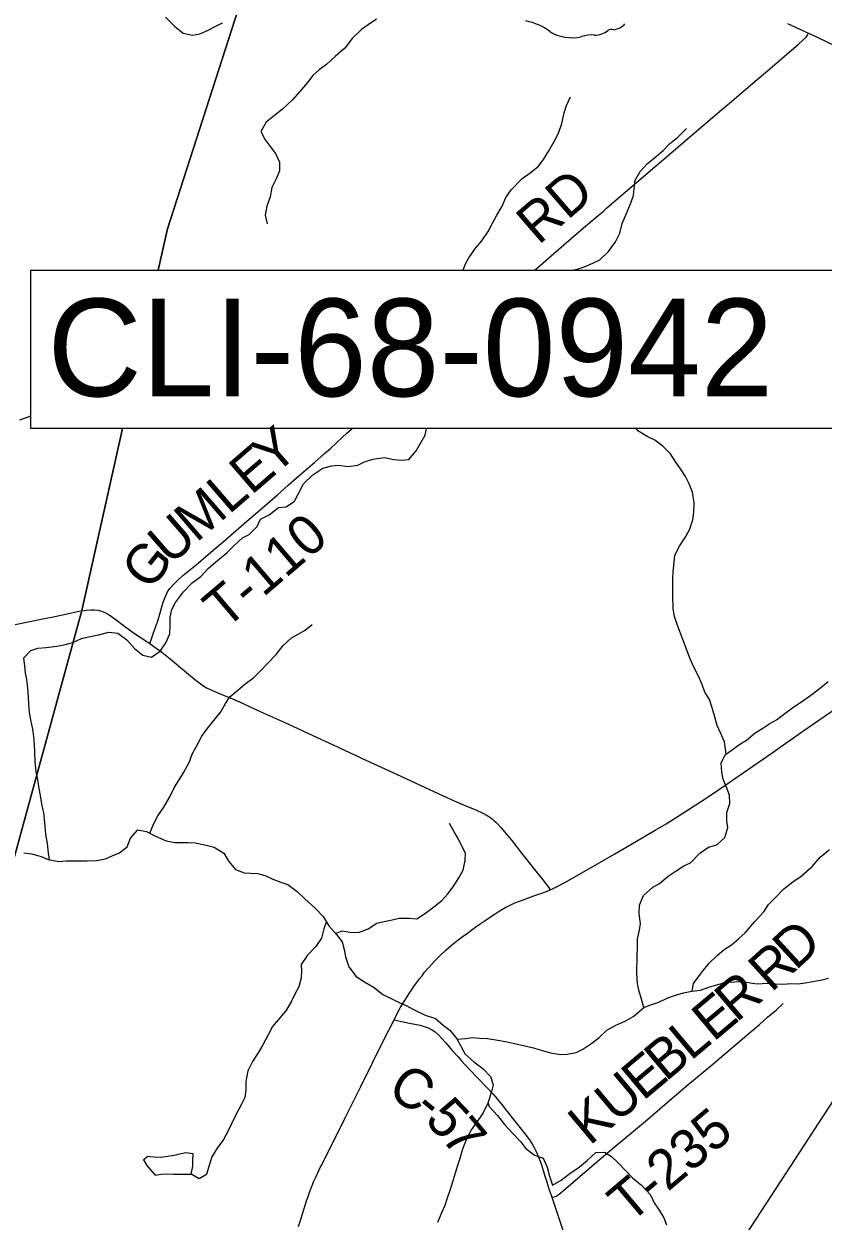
# Model space of a CAD drawing. Extents: x 0 to 34, y 0 to 22.
# Drawn here: x 3.586 to 4.732, y 15.651 to 17.368 of the extents above; entities that cross this region are included whole.
import ezdxf

# ---------------------------------------------------------------- set-up
doc = ezdxf.new("R2010")
doc.units = 0
for name, color, linetype in [('GM_X_County_Road', 7, 'Continuous'), ('GM_X_County_Road_Text', 7, 'Continuous'), ('GM_X_Minor_Lake', 7, 'Continuous'), ('GM_X_Minor_River', 7, 'Continuous'), ('GM_X_Rail_Line', 7, 'Continuous'), ('GM_X_State_Route', 7, 'Continuous'), ('GM_X_State_Shield', 7, 'Continuous'), ('GM_X_Township_Road', 7, 'Continuous'), ('GM_X_Township_Road_Text', 7, 'Continuous'), ('GM_X_US_Route', 7, 'Continuous'), ('SH_Text', 7, 'Continuous')]:
    doc.layers.add(name, color=color, linetype=linetype)

msp = doc.modelspace()

# ---------------------------------------------------------------- linework, layer by layer
at = {"layer": 'GM_X_County_Road'}
for points in [[(4.117, 15.9393), (4.1256, 15.9374), (4.1389, 15.9345), (4.1542, 15.9314), (4.1602, 15.9298), (4.1656, 15.9278), (4.1707, 15.9253), (4.1759, 15.9217), (4.1806, 15.9175), (4.185, 15.913), (4.1911, 15.906), (4.2004, 15.8951), (4.2086, 15.8859), (4.2107, 15.8835), (4.2132, 15.8809), (4.2251, 15.8681), (4.2504, 15.8416), (4.2588, 15.8324), (4.2617, 15.8292), (4.2647, 15.8256), (4.268, 15.8217), (4.2713, 15.8178), (4.2755, 15.8124), (4.3048, 15.7753), (4.3111, 15.7668), (4.3136, 15.7631), (4.3159, 15.7595), (4.3181, 15.7553), (4.3203, 15.7512), (4.3222, 15.7468), (4.3242, 15.742), (4.3262, 15.7365), (4.3286, 15.7297), (4.3332, 15.7148), (4.3348, 15.7096), (4.3368, 15.7033), (4.3383, 15.6982), (4.3397, 15.6941), (4.3429, 15.6846)], [(4.3429, 15.6846), (4.3609, 15.6317)]]:
    msp.add_lwpolyline(points, dxfattribs=at)
at = {"layer": 'GM_X_Minor_Lake'}
for points in [[(3.8258, 15.7177), (3.8283, 15.7291), (3.8284, 15.7371), (3.8289, 15.7469), (3.8183, 15.7486), (3.8095, 15.7464), (3.8016, 15.7446), (3.7924, 15.7429), (3.7822, 15.7415), (3.7727, 15.742), (3.767, 15.7428)], [(3.767, 15.7428), (3.764, 15.7433), (3.7579, 15.7384), (3.7627, 15.73), (3.7675, 15.7238), (3.7742, 15.7165), (3.783, 15.7179), (3.7913, 15.7182), (3.8008, 15.7177), (3.8103, 15.718), (3.8258, 15.7177)]]:
    msp.add_lwpolyline(points, dxfattribs=at)
at = {"layer": 'GM_X_Minor_River'}
for points in [[(3.7893, 17.3776), (3.8024, 17.3642), (3.8144, 17.3545), (3.828, 17.3517), (3.8386, 17.3534), (3.8493, 17.3582), (3.8615, 17.3645), (3.8711, 17.3693)], [(4.0918, 17.3746), (4.0799, 17.3664), (4.0704, 17.3597), (4.0569, 17.347), (4.0465, 17.3327), (4.0323, 17.3212), (4.02, 17.3096), (4.01, 17.3025), (4.0004, 17.2939), (3.993, 17.2837), (3.9815, 17.2702), (3.9711, 17.259), (3.9572, 17.2455), (3.9457, 17.2365), (3.9338, 17.2268), (3.9257, 17.2133), (3.9319, 17.2014), (3.9394, 17.1918), (3.9468, 17.1819), (3.9527, 17.1693), (3.9525, 17.1571), (3.9486, 17.1465), (3.9419, 17.133), (3.9391, 17.1197), (3.9347, 17.1065), (3.9323, 17.0936), (3.9351, 17.081)], [(4.2159, 17.0143), (4.219, 17.0225), (4.2241, 17.0323), (4.2338, 17.0462), (4.2427, 17.0567), (4.2519, 17.0699), (4.2582, 17.0819), (4.2644, 17.0933), (4.2718, 17.1064), (4.2773, 17.1185), (4.285, 17.1298), (4.3004, 17.1459), (4.3119, 17.1541), (4.3234, 17.1634), (4.3312, 17.1732), (4.3389, 17.1856), (4.3463, 17.1992), (4.3526, 17.2109), (4.3573, 17.2249), (4.3606, 17.24), (4.3642, 17.2506), (4.37, 17.263)], [(4.3743, 17.0143), (4.3763, 17.015), (4.3873, 17.0183), (4.4018, 17.0246), (4.4121, 17.0294), (4.4244, 17.0413), (4.4345, 17.0552), (4.4407, 17.0677), (4.444, 17.0813), (4.4499, 17.0949), (4.4561, 17.1096), (4.4601, 17.1217), (4.461, 17.1312), (4.4627, 17.1437), (4.4697, 17.1561), (4.4801, 17.1674), (4.4928, 17.1775), (4.5027, 17.186), (4.5116, 17.1958), (4.5239, 17.2051), (4.5362, 17.2175)], [(3.5803, 16.7996), (3.5936, 16.8048), (3.596, 16.8059)], [(3.6228, 16.1689), (3.6217, 16.1784), (3.62, 16.1921), (3.6179, 16.205), (3.6166, 16.2164), (3.6156, 16.227), (3.6146, 16.2365), (3.6124, 16.2461), (3.6107, 16.2579), (3.6075, 16.2738), (3.6062, 16.2841), (3.604, 16.2944), (3.6024, 16.31), (3.6018, 16.3233), (3.6016, 16.3339), (3.6006, 16.3457), (3.5989, 16.3563), (3.596, 16.3693), (3.5943, 16.3799), (3.5933, 16.3917), (3.5927, 16.4024), (3.5921, 16.4149), (3.5904, 16.4271), (3.5887, 16.4366), (3.5877, 16.4465), (3.5863, 16.4586), (3.596, 16.4691), (3.6063, 16.4724), (3.618, 16.4734), (3.6336, 16.4751), (3.6439, 16.4772), (3.6564, 16.4805), (3.669, 16.486), (3.6793, 16.4885), (3.6949, 16.4917), (3.7082, 16.4953), (3.7207, 16.4936), (3.7338, 16.484), (3.745, 16.472), (3.7566, 16.462), (3.7691, 16.4596), (3.7814, 16.4681), (3.7895, 16.4798), (3.7954, 16.493), (3.7959, 16.5044), (3.7957, 16.5169), (3.7985, 16.5279), (3.8036, 16.5377), (3.8152, 16.5531), (3.8275, 16.5658), (3.8398, 16.5751), (3.851, 16.5868), (3.864, 16.598), (3.8775, 16.6096), (3.8871, 16.6193), (3.8994, 16.6305), (3.9093, 16.6353), (3.9205, 16.6466), (3.9255, 16.6571), (3.9381, 16.6634), (3.9512, 16.6739), (3.9622, 16.6748), (3.9741, 16.683), (3.9799, 16.694), (3.9873, 16.7079), (4.0004, 16.721), (4.015, 16.7303), (4.0279, 16.7339), (4.0374, 16.7346), (4.051, 16.7329), (4.0651, 16.7349), (4.0746, 16.7394), (4.0864, 16.7434), (4.1031, 16.7458), (4.1168, 16.743), (4.127, 16.7421), (4.138, 16.7427), (4.1484, 16.7551), (4.1542, 16.7656), (4.1616, 16.7777), (4.1633, 16.7873)], [(4.593, 16.3203), (4.5905, 16.3379), (4.585, 16.3509), (4.5802, 16.3612), (4.5774, 16.3719), (4.573, 16.3867), (4.569, 16.3985), (4.5627, 16.4093), (4.5591, 16.4188), (4.5543, 16.4303), (4.5466, 16.4448), (4.5414, 16.457), (4.536, 16.4707), (4.5308, 16.4845), (4.5265, 16.4963), (4.5228, 16.5062), (4.5192, 16.5177), (4.5171, 16.5287), (4.5166, 16.5477), (4.5168, 16.5617), (4.5166, 16.5724), (4.5171, 16.5819), (4.5184, 16.5955), (4.5193, 16.6057), (4.526, 16.6186), (4.5345, 16.631), (4.5407, 16.6419), (4.5451, 16.6563), (4.5468, 16.6673), (4.547, 16.6809), (4.5449, 16.6961), (4.5398, 16.708), (4.5346, 16.7183), (4.5276, 16.7294), (4.5209, 16.739), (4.5131, 16.7512), (4.5023, 16.762), (4.4906, 16.7705), (4.4797, 16.776), (4.4673, 16.7837), (4.4638, 16.7873)], [(3.7667, 16.2067), (3.7725, 16.2207), (3.7783, 16.2317), (3.7868, 16.2444), (3.7954, 16.2588), (3.802, 16.2731), (3.8086, 16.2833), (3.8156, 16.2945), (3.823, 16.3085), (3.8277, 16.3202), (3.8359, 16.336), (3.8414, 16.3462), (3.8491, 16.3564), (3.8584, 16.3684), (3.8688, 16.3808), (3.8754, 16.3928), (3.8816, 16.4026), (3.8932, 16.4127), (3.9028, 16.4205), (3.9158, 16.4302), (3.9254, 16.4396), (3.9354, 16.4501), (3.9477, 16.4632), (3.9578, 16.476), (3.9701, 16.4872), (3.9796, 16.4924), (3.9896, 16.4983), (3.9996, 16.5062)], [(4.475, 15.9568), (4.4718, 15.9686), (4.4678, 15.9819), (4.466, 15.9915), (4.4651, 16.0063), (4.4655, 16.031), (4.466, 16.0435), (4.4658, 16.0552), (4.469, 16.0677), (4.4703, 16.0772), (4.4682, 16.0913), (4.4688, 16.1034), (4.4747, 16.1174), (4.4881, 16.1293), (4.4977, 16.1349), (4.51, 16.145), (4.5199, 16.1521), (4.5326, 16.1599), (4.5421, 16.1643), (4.5552, 16.1782), (4.5675, 16.1867), (4.5796, 16.1904), (4.5912, 16.2005), (4.5955, 16.2148), (4.5942, 16.2243), (4.594, 16.2365), (4.5983, 16.2497), (4.5977, 16.2615), (4.5941, 16.2714), (4.589, 16.2844), (4.5868, 16.2943), (4.5859, 16.3076), (4.5921, 16.3196), (4.6017, 16.3264), (4.6113, 16.3334), (4.622, 16.3401), (4.6347, 16.351), (4.6458, 16.3573), (4.6557, 16.364), (4.6653, 16.3695), (4.6772, 16.3785), (4.6887, 16.387), (4.6982, 16.3934), (4.7124, 16.4034), (4.7262, 16.4139), (4.7393, 16.4247)], [(3.5861, 16.1785), (3.5974, 16.1772), (3.611, 16.1736), (3.6212, 16.1693), (3.6363, 16.1664), (3.6466, 16.1674), (3.6769, 16.167), (3.6909, 16.1675), (3.7031, 16.17), (3.713, 16.1745), (3.7233, 16.1789), (3.7344, 16.1871), (3.7392, 16.1995), (3.7496, 16.2115), (3.7621, 16.2091), (3.7748, 16.2025), (3.7903, 16.1958), (3.8024, 16.1937), (3.8217, 16.1935), (3.8316, 16.193), (3.8456, 16.1901), (3.8592, 16.1869)], [(4.0332, 16.0629), (4.0425, 16.0667), (4.0534, 16.065), (4.0659, 16.0645), (4.08, 16.0696), (4.0923, 16.0778), (4.1029, 16.0803), (4.114, 16.0824), (4.1243, 16.085), (4.1387, 16.0848), (4.1496, 16.0839), (4.1619, 16.092), (4.1738, 16.1014), (4.1853, 16.1103), (4.1941, 16.1201), (4.2015, 16.1298), (4.21, 16.143), (4.2159, 16.1536), (4.2187, 16.1676), (4.2193, 16.1782), (4.2141, 16.1881), (4.2093, 16.1981), (4.203, 16.2088), (4.1964, 16.221)], [(3.8592, 16.1869), (3.8727, 16.1784), (3.8801, 16.1661), (3.8894, 16.155), (3.9019, 16.1502), (3.9113, 16.1497), (3.9216, 16.1492), (3.9329, 16.1457), (3.9431, 16.141), (3.9544, 16.1366), (3.9646, 16.1334), (3.9781, 16.1234), (3.9889, 16.1126), (4.0039, 16.0995), (4.0151, 16.0872), (4.0232, 16.0738), (4.0344, 16.0615), (4.0426, 16.0511), (4.0455, 16.0401), (4.0472, 16.0294), (4.052, 16.0153), (4.0627, 16.0015), (4.0744, 15.9938), (4.0883, 15.9856), (4.101, 15.9756), (4.1138, 15.9693), (4.1244, 15.9639), (4.1342, 15.9595), (4.1459, 15.9537), (4.1617, 15.9459), (4.1764, 15.9411), (4.1872, 15.9315), (4.197, 15.9241), (4.2067, 15.9119), (4.2122, 15.9023), (4.2189, 15.8901), (4.2312, 15.8789), (4.2443, 15.8692), (4.2552, 15.858), (4.2592, 15.8458), (4.256, 15.8345), (4.2512, 15.8194), (4.2449, 15.8058), (4.2368, 15.7949), (4.2279, 15.7817), (4.2209, 15.7685), (4.215, 15.7538), (4.2114, 15.7402), (4.2078, 15.73), (4.2046, 15.7194), (4.2002, 15.705), (4.1971, 15.6945), (4.1931, 15.6835), (4.1895, 15.6729), (4.1856, 15.6631), (4.1793, 15.6484)], [(4.5441, 15.9802), (4.5464, 15.9915), (4.5588, 16.008), (4.5685, 16.0204), (4.5808, 16.032), (4.5904, 16.0399), (4.6007, 16.0466), (4.6107, 16.0555), (4.6203, 16.0641), (4.6342, 16.0803), (4.6469, 16.0942), (4.6539, 16.1047), (4.6639, 16.1144), (4.6758, 16.1272), (4.6888, 16.1369), (4.7007, 16.1451), (4.7165, 16.1589), (4.7276, 16.1724), (4.7411, 16.1836)], [(4.0198, 16.0794), (4.0163, 16.0697), (4.0127, 16.0565), (4.0046, 16.0444), (3.993, 16.0317), (3.9838, 16.0185), (3.984, 16.009), (3.9839, 15.9996), (3.9803, 15.9867), (3.974, 15.975), (3.9693, 15.9652), (3.9616, 15.952), (3.9507, 15.9393), (3.9426, 15.9295), (3.9364, 15.9174), (3.929, 15.9035), (3.922, 15.8918), (3.9142, 15.8794), (3.9072, 15.8662), (3.9043, 15.8507), (3.9042, 15.8382), (3.9032, 15.8275), (3.8978, 15.8174), (3.89, 15.803), (3.8841, 15.7898), (3.879, 15.78), (3.8724, 15.7676), (3.8631, 15.7552), (3.8557, 15.7424), (3.851, 15.7273), (3.8478, 15.7171), (3.8373, 15.7112), (3.8258, 15.7177)], [(4.207, 15.9112), (4.2196, 15.9124), (4.2291, 15.9138), (4.2393, 15.9129), (4.2507, 15.9124), (4.2658, 15.9099), (4.2768, 15.9082), (4.2896, 15.9054), (4.3043, 15.9018), (4.3168, 15.899), (4.3293, 15.895), (4.3414, 15.8918), (4.3554, 15.8893), (4.3652, 15.89), (4.3778, 15.8924), (4.3877, 15.8972), (4.4007, 15.9058), (4.4111, 15.914), (4.4222, 15.9241), (4.4348, 15.9315), (4.4482, 15.937), (4.4608, 15.9445), (4.475, 15.9568), (4.4849, 15.9608), (4.4964, 15.9645), (4.5093, 15.9708), (4.5204, 15.9744), (4.5318, 15.9777), (4.544, 15.9802), (4.5565, 15.9819), (4.5683, 15.9859), (4.5809, 15.9899), (4.5931, 15.9931), (4.6056, 15.9937), (4.617, 15.994), (4.6276, 15.9923), (4.6374, 15.9906), (4.6522, 15.9916), (4.6636, 15.991), (4.6742, 15.9905), (4.6867, 15.9911), (4.6962, 15.991), (4.7064, 15.992), (4.7171, 15.9941), (4.73, 15.9966), (4.7399, 15.9987)], [(4.2516, 15.8207), (4.2534, 15.8148), (4.2654, 15.8021), (4.2754, 15.7891), (4.2866, 15.7768), (4.2982, 15.7645), (4.3052, 15.7549), (4.3184, 15.7452), (4.3308, 15.7405), (4.3363, 15.7279), (4.3399, 15.7149), (4.3439, 15.7019), (4.3565, 15.709), (4.3696, 15.7194), (4.3803, 15.7265), (4.3937, 15.7373), (4.406, 15.7489), (4.4185, 15.7491), (4.4287, 15.7433), (4.4384, 15.7341), (4.4492, 15.7225), (4.459, 15.7125), (4.4717, 15.7021), (4.4844, 15.6883), (4.4899, 15.6768), (4.497, 15.6661), (4.5036, 15.655), (4.5073, 15.6451)]]:
    msp.add_lwpolyline(points, dxfattribs=at)
at = {"layer": 'GM_X_Rail_Line'}
msp.add_lwpolyline([(4.6156, 15.6215), (4.8241, 15.9416), (4.9114, 16.0746), (4.9613, 16.1518), (5.1119, 16.3828), (5.1792, 16.4864), (5.2122, 16.5384), (5.2228, 16.5564), (5.239, 16.5855), (5.2512, 16.6096), (5.2649, 16.6381), (5.2772, 16.6659), (5.2853, 16.685), (5.2949, 16.71), (5.309, 16.7496), (5.3263, 16.8047), (5.3317, 16.8237), (5.3347, 16.8369), (5.3368, 16.8453), (5.3438, 16.8662), (5.3662, 16.9437), (5.3876, 17.012), (5.4635, 17.2672), (5.5484, 17.5486)], dxfattribs=at)
at = {"layer": 'GM_X_State_Route'}
msp.add_lwpolyline([(4.6811, 17.3682), (4.7112, 17.3543), (4.7144, 17.3528), (4.7475, 17.337), (4.7768, 17.3234), (4.8026, 17.3112), (4.8263, 17.3003), (4.8617, 17.2836), (4.8866, 17.2723), (4.9103, 17.2614), (4.9493, 17.2435), (4.9689, 17.2342), (4.9927, 17.2234), (5.0118, 17.2144), (5.0259, 17.208), (5.0422, 17.2007)], dxfattribs=at)
at = {"layer": 'GM_X_State_Shield'}
for centre, major_axis, start_param, end_param in [((4.2865, 17.3107), (0.079, 0), 0.823519, 1.323587), ((4.4254, 17.3812), (0.0282, 0), 4.937069, 5.64225), ((4.3719, 17.388), (0.0501, 0), 4.026481, 4.996735), ((4.4008, 17.3189), (0.0412, 0), 1.495662, 1.94098), ((4.4045, 17.3731), (0.0267, 0), 4.691044, 5.507374), ((4.4287, 17.3537), (0.00752, 0), 1.147584, 2.315152)]:
    msp.add_ellipse(centre, major_axis=major_axis, ratio=0.8, start_param=start_param, end_param=end_param, dxfattribs=at)
at = {"layer": 'GM_X_Township_Road'}
for points in [[(3.7787, 17.0143), (3.7921, 17.074), (3.9903, 17.6899), (4.0744, 17.9948), (4.1901, 18.4135), (4.1943, 18.4289), (4.2897, 18.7747), (4.3389, 18.9527), (4.4789, 19.5742), (4.4849, 19.6021), (4.4654, 19.6041), (3.501, 19.6889), (3.4805, 19.8366), (3.1735, 19.8394), (3.1019, 19.912), (2.3144, 20.5665), (2.1, 20.7431), (2.1, 15.597), (2.2517, 15.5643), (3.1228, 15.3686), (3.3385, 15.3189), (3.6691, 16.5264), (3.7277, 16.7873)], [(3.7277, 16.7873), (3.6691, 16.5264), (3.3385, 15.3189), (3.2153, 14.8228), (3.0598, 14.2522), (3.3693, 14.1947), (3.882, 14.1), (5.5061, 14.1), (5.6307, 14.246), (5.7089, 14.3412), (6.2381, 14.9624), (6.7874, 15.6255), (6.8121, 15.6375), (7.6646, 16.0363), (8.8399, 16.5839), (8.8447, 16.5834), (8.8816, 16.5789), (8.8995, 16.5764), (8.9, 16.5763), (8.9, 19.1426)], [(3.9903, 17.6899), (3.7921, 17.074), (3.7787, 17.0143)], [(4.3182, 17.0143), (4.3225, 17.0179), (4.3459, 17.0383), (4.385, 17.0722), (4.4094, 17.093), (4.4165, 17.0988), (4.4222, 17.1038), (4.4745, 17.1487), (4.5171, 17.185), (4.5444, 17.2085), (4.5865, 17.2443), (4.6006, 17.2565), (4.6313, 17.2828), (4.6555, 17.3033), (4.6969, 17.3389), (4.7077, 17.3488), (4.7089, 17.3502), (4.7095, 17.3514), (4.7112, 17.3543)], [(3.7666, 16.479), (3.7698, 16.4869), (3.7726, 16.4956), (3.7754, 16.5034), (3.7785, 16.513), (3.786, 16.5384), (3.7895, 16.5477), (3.792, 16.5529), (3.7953, 16.5577), (3.7996, 16.5627), (3.8053, 16.5685), (3.8143, 16.5765), (3.833, 16.5919), (3.8507, 16.6069), (3.8752, 16.6276), (3.8944, 16.6442), (3.9058, 16.6543), (3.9282, 16.6734), (3.9428, 16.6861), (3.9498, 16.692), (3.9653, 16.7061), (3.9769, 16.7164), (3.9934, 16.7303), (4.0032, 16.7389), (4.0171, 16.7514), (4.0251, 16.7583), (4.0355, 16.7679), (4.0426, 16.7747), (4.0491, 16.7805), (4.0569, 16.7873)], [(3.5575, 16.503), (3.5922, 16.5099), (3.6135, 16.5142), (3.6305, 16.5177), (3.6481, 16.5215), (3.6651, 16.5252), (3.6693, 16.5259)], [(3.6693, 16.5259), (3.6756, 16.5269), (3.6825, 16.5275), (3.6875, 16.5274), (3.6925, 16.5267), (3.6979, 16.5252), (3.7032, 16.523), (3.7087, 16.52), (3.7168, 16.5142), (3.7306, 16.5037), (3.7447, 16.4934), (3.7623, 16.4819), (3.7666, 16.479)], [(3.7666, 16.479), (3.7706, 16.4763), (3.7841, 16.4663), (3.7959, 16.457), (3.8164, 16.4399), (3.8306, 16.4279), (3.8368, 16.423), (3.8428, 16.4185), (3.8479, 16.4154), (3.8521, 16.4134), (3.8574, 16.4109), (3.8678, 16.4066), (3.8851, 16.3998), (3.8954, 16.3954), (3.9106, 16.3883), (3.9302, 16.3791), (3.9518, 16.3696), (3.9648, 16.3638), (4.0003, 16.3472), (4.0296, 16.3336), (4.0763, 16.3118), (4.1203, 16.2915), (4.1738, 16.2665), (4.1935, 16.2574), (4.2066, 16.2517), (4.2233, 16.2448), (4.2342, 16.2403), (4.244, 16.2358), (4.2504, 16.2324), (4.2529, 16.2308), (4.2557, 16.2288), (4.2586, 16.2265), (4.2606, 16.2248), (4.2629, 16.2226), (4.266, 16.2194), (4.2699, 16.2148), (4.2751, 16.2087), (4.2856, 16.1963), (4.2998, 16.1781), (4.3181, 16.1547), (4.3304, 16.1399), (4.3368, 16.1313), (4.3378, 16.1297), (4.3406, 16.1256)], [(4.3429, 15.6846), (4.3452, 15.6849), (4.3477, 15.6855), (4.3493, 15.6862), (4.3509, 15.6873), (4.3534, 15.6891), (4.3865, 15.7174), (4.4144, 15.7411), (4.4352, 15.7589), (4.4601, 15.7794), (4.4772, 15.7939), (4.5184, 15.829), (4.5382, 15.8459), (4.5711, 15.8734), (4.6228, 15.9172), (4.6407, 15.9326), (4.6524, 15.9428), (4.6651, 15.9537), (4.6748, 15.9625)]]:
    msp.add_lwpolyline(points, dxfattribs=at)
at = {"layer": 'GM_X_US_Route'}
for points in [[(4.6589, 16.3223), (4.6622, 16.3246), (4.7045, 16.3541), (4.7822, 16.4079), (4.8075, 16.425), (4.8192, 16.4329), (4.8217, 16.4345), (4.8306, 16.4403), (4.8413, 16.4467), (4.8507, 16.4519), (4.8608, 16.4575), (4.8729, 16.4638), (4.8914, 16.4725), (4.9318, 16.4902), (4.952, 16.4993)], [(4.5361, 16.2391), (4.5561, 16.2519), (4.5758, 16.2649), (4.6173, 16.2935), (4.6589, 16.3223)], [(4.0125, 15.7299), (4.0314, 15.7675), (4.0467, 15.7986), (4.0692, 15.8436), (4.1018, 15.9093), (4.117, 15.9393), (4.1215, 15.9481), (4.1259, 15.9562), (4.1312, 15.9653), (4.1347, 15.9709), (4.1385, 15.9769), (4.1417, 15.9816), (4.1455, 15.9871), (4.1492, 15.9921), (4.1535, 15.9981), (4.157, 16.0025), (4.1608, 16.0073), (4.1672, 16.0149), (4.1747, 16.0231), (4.1786, 16.027), (4.183, 16.0315), (4.1915, 16.0395), (4.1995, 16.0464), (4.2087, 16.0537), (4.2146, 16.0581), (4.2221, 16.0637), (4.2347, 16.0728), (4.249, 16.0827), (4.2568, 16.0878), (4.2604, 16.0902), (4.2692, 16.096), (4.2771, 16.1007), (4.2832, 16.1038), (4.2899, 16.1068), (4.298, 16.11), (4.3174, 16.1168), (4.3261, 16.1199), (4.3354, 16.1234), (4.3406, 16.1256), (4.344, 16.1271), (4.3525, 16.1312), (4.3591, 16.1348), (4.3662, 16.1386), (4.4088, 16.1629), (4.4335, 16.1773), (4.4566, 16.1907), (4.4915, 16.211), (4.5069, 16.2204), (4.5361, 16.2391)], [(3.9799, 15.6426), (3.9845, 15.6576), (3.9914, 15.6795), (3.9937, 15.6859), (3.9961, 15.6929), (3.9995, 15.7016), (4.0021, 15.7076), (4.0047, 15.7135), (4.0116, 15.7281), (4.0125, 15.7299)]]:
    msp.add_lwpolyline(points, dxfattribs=at)
at = {"layer": 'SH_Text'}
msp.add_lwpolyline([(3.596, 17.0143), (4.7456, 17.0143), (4.7456, 16.9576), (5.5484, 17.6156), (4.7456, 16.844), (4.7456, 16.7873), (3.596, 16.7873)], close=True, dxfattribs=at)

# ---------------------------------------------------------------- texts
at = {"layer": 'GM_X_County_Road_Text'}
for s, rotation, p in [('C', 326.9042, (4.1049, 15.8323)), ('-', 320.4393, (4.1426, 15.8078)), ('5', 313.6531, (4.1593, 15.7942)), ('7', 309.9595, (4.1828, 15.7696))]:
    msp.add_text(s, height=0.0568, rotation=rotation, dxfattribs=at).set_placement(p)
at = {"layer": 'GM_X_Township_Road_Text'}
for s, height, rotation, p in [('RD', 0.05682, 40.8162, (4.3239, 17.0495)), ('Y', 0.0568, 40.816, (3.9445, 16.7187)), ('E', 0.0568, 40.8134, (3.9123, 16.6909)), ('L', 0.0568, 40.8128, (3.8801, 16.6631)), ('M', 0.0568, 40.8172, (3.8334, 16.6228)), ('U', 0.0568, 40.9771, (3.7957, 16.59)), ('T-110', 0.05682, 40.4563, (3.8746, 16.498)), ('G', 0.0568, 51.6204, (3.7666, 16.5529)), ('D', 0.0568, 42.5853, (4.6926, 16.009)), ('R', 0.0568, 42.1723, (4.6577, 15.9774)), ('R', 0.0568, 40.4597, (4.6077, 15.9343)), ('E', 0.0568, 40.0158, (4.5748, 15.9067)), ('B', 0.0568, 40.0107, (4.5065, 15.8494)), ('L', 0.0568, 40.0072, (4.5422, 15.8794)), ('E', 0.0568, 40.0086, (4.4739, 15.822)), ('U', 0.0568, 40.013, (4.4356, 15.7899)), ('K', 0.0568, 40.0094, (4.3973, 15.7577)), ('T-235', 0.05682, 40.2367, (4.4546, 15.6455))]:
    msp.add_text(s, height=height, rotation=rotation, dxfattribs=at).set_placement(p)
at = {"layer": 'SH_Text'}
msp.add_text('CLI-68-0942', height=0.14, dxfattribs=at).set_placement((3.62, 16.8336))

doc.saveas('drawing.dxf')
